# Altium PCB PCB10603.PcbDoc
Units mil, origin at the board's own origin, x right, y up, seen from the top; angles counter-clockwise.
Board outline 700 x 700 mil, 2 copper layers (Top Layer, Bottom Layer); 11 components, 0 nets, 31 pads, 0 vias.
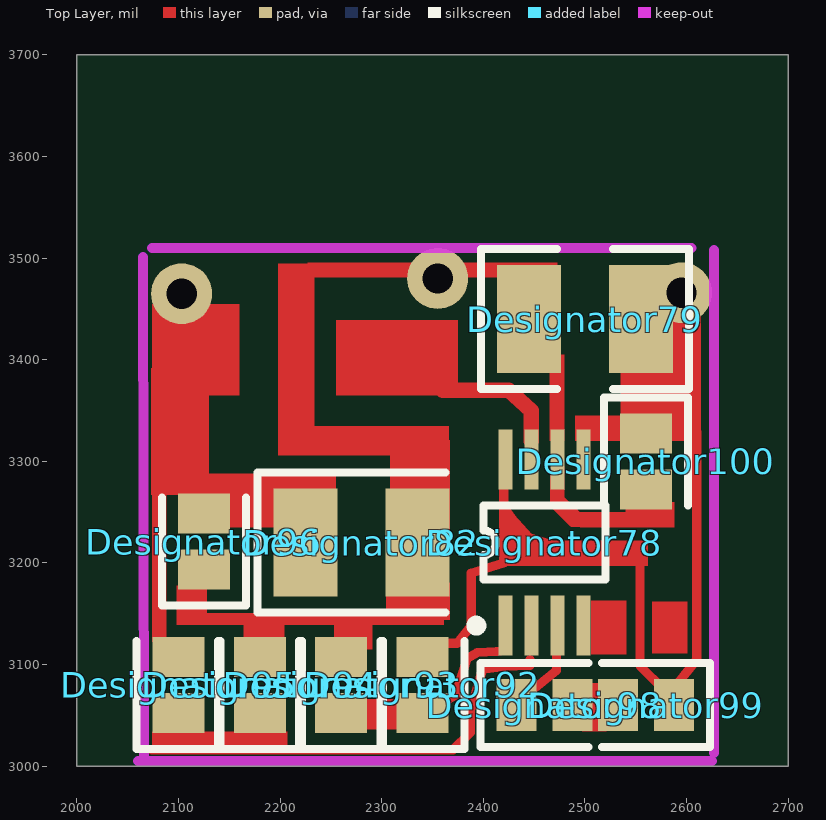
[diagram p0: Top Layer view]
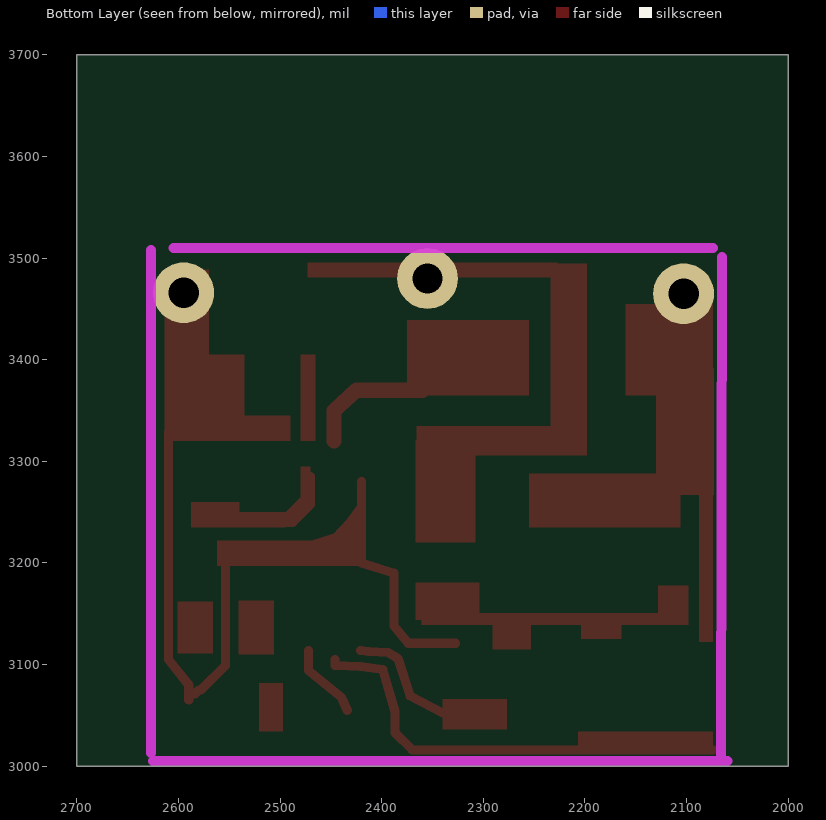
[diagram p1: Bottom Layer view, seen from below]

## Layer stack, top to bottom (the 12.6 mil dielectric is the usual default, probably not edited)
Top Layer: signal copper 1.4
Dielectric: dielectric 12.6, FR-4, Dk 4.8
Bottom Layer: signal copper 1.4

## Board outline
2000,3000 2700,3000 2700,3700 2000,3700

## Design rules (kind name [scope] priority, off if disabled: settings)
Clearance [All] p1: gap=8
ComponentClearance [All] p1: gap=10 collisioncheckmode=0
PolygonConnect [All] p1: connectstyle=Relief reliefconductorwidth=10 reliefentries=4 polygonreliefangle="90 Angle"
RoutingLayers [All] p1: top layer=Horizontal bottom layer=Vertical
RoutingVias [All] p1: holewidth=25 width=40 viastyle="Through Hole" minholewidth=28 minwidth=50 maxholewidth=28 maxwidth=50
SolderMaskExpansion [All] p1: expansion=4
TestPointUsage [All] p1: valid=0 allowmultiple=FALSE
Testpoint [All] p1: side=15 testpointundercomponent=TRUE minsize=40 maxsize=100 preferedsize=60 minholesize=0 maxholesize=40 preferedholesize=32 testpointgrid=1 style=1023 order=1234567890
Width [All] p1: maxlimit=9 minlimit=9 preferedwidth=9
16 further rules are at their usual default settings.

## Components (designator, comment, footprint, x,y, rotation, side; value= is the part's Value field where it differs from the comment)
Designator78 "Comment" UMAX8 2460,3220 r0 top
Designator79 "Comment" CR3225-1210 2500,3440 r0 top
Designator82 "Comment" CC3225-1210 2280,3220 r0 top
Designator92 "Comment" CC1310-0504 2340,3080 r90 top
Designator93 "Comment" CC1310-0504 2260,3080 r90 top
Designator94 "Comment" CC1310-0504 2180,3080 r90 top
Designator95 "Comment" CC1310-0504 2100,3080 r90 top
Designator96 "Comment" CC1310-0504 2125,3221 r90 top
Designator98 "Comment" CC1310-0504 2460,3060 r0 top
Designator99 "Comment" CC1310-0504 2560,3060 r180 top
Designator100 "Comment" CC1310-0504 2560,3300 r270 top

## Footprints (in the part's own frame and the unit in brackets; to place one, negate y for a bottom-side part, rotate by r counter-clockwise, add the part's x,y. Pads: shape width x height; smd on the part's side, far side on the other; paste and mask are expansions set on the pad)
CC1310-0504 [mm]
  rect 1x1.3 smd: 1(-0.7,0) 2(0.7,0)
  silkscreen extent -1.6,-1.05 1.1,1.05
CC3225-1210 [mm]
  rect 1.6x2.7 smd: 1(-1.4,0) 2(1.4,0)
  silkscreen extent -2.6,-1.75 2.1,1.75
CR3225-1210 [mm]
  rect 1.6x2.7 smd: 1(-1.4,0) 2(1.4,0)
  silkscreen extent -2.6,-1.75 2.6,1.75
UMAX8 [mm] "Shrink Small Outline; 8 Leads; Body Width 3 mm; Pitch 0.65 mm"
  rect 0.35x1.5 smd: 1(-0.975,-2.075) 2(-0.325,-2.075) 3(0.325,-2.075) 4(0.975,-2.075) 5(0.975,2.075) 6(0.325,2.075) 7(-0.325,2.075) 8(-0.975,2.075)
  silkscreen extent -1.82,-2.2 1.52,0.92

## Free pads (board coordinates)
  round 60 hole 30: 0(2595,3466) 1(2103,3465) 2(2355,3480)

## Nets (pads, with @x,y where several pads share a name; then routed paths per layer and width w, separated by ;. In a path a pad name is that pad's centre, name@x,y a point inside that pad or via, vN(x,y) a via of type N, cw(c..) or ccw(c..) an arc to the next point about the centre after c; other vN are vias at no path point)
pads on no net: Designator78.1 Designator78.2 Designator78.3 Designator78.4 Designator78.5 Designator78.6 Designator78.7 Designator78.8 Designator79.1 Designator79.2 Designator82.1 Designator82.2 Designator92.1 Designator92.2 Designator93.1 Designator93.2 Designator94.1 Designator94.2 Designator95.1 Designator95.2 Designator96.1 Designator96.2 Designator98.1 Designator98.2 Designator99.1 Designator99.2 Designator100.1 Designator100.2
copper on no net: | length 1681.5
  Top Layer w9: 2074,3016 2370,3016 2387,3033 2387,3054 2399,3095 2421,3098 2446,3099 2446,3105 ; 2327.56,3121 2374,3121 2388,3138 2388,3190 2420,3200 2420,3255 ; 2340,3052.44 2372,3069 2384,3106 2394,3112 2413,3113 2421,3114 ; 2420,3280 2420,3255 ; 2434,3055 2440,3068 2472,3094.28 2472,3114 ; 2445,3345.72 2447,3320 ; 2470,3285 2470,3257.67 2487.67,3240 2555.97,3240 2558.57,3242.6 ; 2526,3217 2471,3217 2445,3225 2431,3240 2420,3255 ; 2553.37,3240 2555.97,3242.6 ; 2554,3208 2554,3099 2578,3075 2580,3075 2584,3071 ; 2590,3065 2590,3080.09 2610,3105.09 2610,3329
  Top Layer w15: 2360,3370 2425,3370 2447,3350 2447,3320

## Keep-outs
Keep-Out Layer:
  lines w10: 2060,3005 2625,3005 ; 2065,3501 2066,3011 ; 2074,3510 2605,3510 ; 2627,3013 2627,3508

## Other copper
Top Layer:
  rectangle: 2277,3036 2340,3066
  rectangle: 2253,3115 2291,3144
  rectangle: 2304,3144 2367,3181
  rectangle: 2098,3146 2128,3178
  rectangle: 2098,3139 2361,3151
  rectangle: 2106,3235 2255,3288
  rectangle: 2073,3267 2130,3392
  rectangle: 2308,3220 2367,3321
  rectangle: 2226,3306 2366,3335
  rectangle: 2198,3306 2234,3495
  rectangle: 2227,3481 2473,3496
  rectangle: 2570,3338 2614,3489
  rectangle: 2495,3235 2588,3250
  region: 2491.89,3236.89 2500,3245 2476.29,3268.71 2468.18,3260.61
  rectangle: 2470,3251.16 2480,3295
  rectangle: 2465,3320 2480,3405
  rectangle: 2535,3330 2585,3405
  rectangle: 2490,3320 2614,3345
  rectangle: 2255,3365 2375,3439
  rectangle: 2074,3365 2160,3455
  rectangle: 2164,3125 2204,3144
  rectangle: 2074,3016 2207,3034
  rectangle: 2074,3122 2088,3271
  rectangle: 2420,3197 2562,3222
  rectangle: 2420,3214 2434,3241
  rectangle: 2420,3217 2443,3233
  rectangle: 2506,3110 2541,3163
  rectangle: 2566,3111 2601,3162
  rectangle: 2497,3034 2521,3082
  rectangle: 2540,3250 2588,3260

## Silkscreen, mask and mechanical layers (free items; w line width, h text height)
Drill Drawing:
  text ".LEGEND" at 2900,3200 h60
  text "Drill Drawing." at 2900,3100 h60

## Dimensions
2065,3501 to 2066,3011 on Mechanical 1
2060,3005 to 2625,3005 on Mechanical 1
